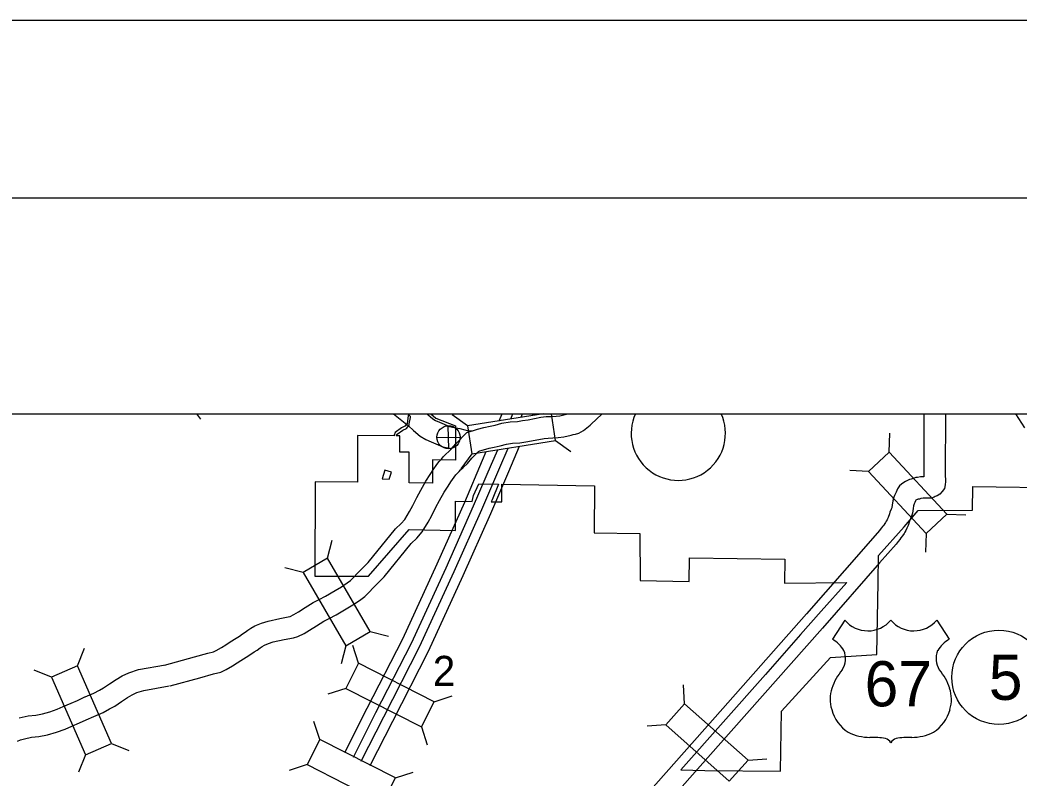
# Model space of a CAD drawing. Extents: x 1369979 to 1371646, y 379997 to 381064.
# Drawn here: x 1370321.9 to 1370431.4, y 380981.1 to 381064.1 of the extents above; entities that cross this region are included whole.
import ezdxf

# ---------------------------------------------------------------- set-up
doc = ezdxf.new("R2010")
doc.units = 0
for name, color, linetype in [('R_Border', 7, 'Continuous'), ('R_Border Notes', 7, 'Continuous'), ('R_No Plot', 7, 'Continuous')]:
    doc.layers.add(name, color=color, linetype=linetype)

msp = doc.modelspace()

# ---------------------------------------------------------------- linework, layer by layer
at = {"layer": 'R_Border'}
msp.add_line((1370040.95, 381044.6), (1371621.85, 381044.6), dxfattribs=at)
at = {"layer": 'R_Border Notes'}
for p, q in [((1370341.21, 381020.95), (1370341.66, 381020.34)), ((1370370.87, 381019.62), (1370369.2, 381020.83)), ((1370379.19, 381020.95), (1370370.87, 381019.62)), ((1370380.52, 381018.03), (1370380.06, 381020.95)), ((1370430.87, 381020.95), (1370431.83, 381019.4)), ((1370368.82, 381017.1), (1370368.77, 381019.64)), ((1370370.87, 381019.62), (1370371.36, 381016.57)), ((1370367.52, 381018.34), (1370370.07, 381018.4)), ((1370417.05, 381016.75), (1370417.12, 381018.81)), ((1370371.36, 381016.57), (1370380.52, 381018.03)), ((1370380.52, 381018.03), (1370382.19, 381016.82)), ((1370371.36, 381016.57), (1370370.15, 381014.9)), ((1370414.78, 381014.64), (1370412.72, 381014.72)), ((1370423.36, 381009.94), (1370425.42, 381009.86)), ((1370421.09, 381007.84), (1370421.01, 381005.78)), ((1370355.56, 381005.12), (1370356.08, 381007.11)), ((1370352.88, 381003.56), (1370350.89, 381004.08)), ((1370412.18, 380998.34), (1370410.83, 380996.25)), ((1370422.24, 380998.34), (1370423.59, 380996.25)), ((1370360.23, 380997.1), (1370362.23, 380996.58)), ((1370328.19, 380993.34), (1370328.94, 380995.26)), ((1370357.56, 380995.54), (1370357.04, 380993.55)), ((1370358.96, 380993.62), (1370358.32, 380995.58)), ((1370325.35, 380992.11), (1370323.43, 380992.86)), ((1370357.56, 380990.87), (1370355.6, 380990.23)), ((1370394.64, 380989.18), (1370394.51, 380991.24)), ((1370367.23, 380989.41), (1370369.19, 380990.05)), ((1370354.71, 380985.28), (1370354.07, 380987.24)), ((1370365.83, 380986.65), (1370366.47, 380984.69)), ((1370392.59, 380986.86), (1370390.53, 380986.74)), ((1370331.9, 380984.84), (1370333.82, 380984.08)), ((1370329.06, 380983.6), (1370328.31, 380981.68)), ((1370353.31, 380982.53), (1370351.34, 380981.89)), ((1370401.59, 380983.02), (1370403.64, 380983.15)), ((1370362.98, 380981.07), (1370364.94, 380981.7))]:
    msp.add_line(p, q, dxfattribs=at)
for points in [[(1370366.85, 381020.95), (1370367.42, 381020.45), (1370369.58, 381019.62), (1370369.58, 381018.43), (1370369.57, 381015.87), (1370367.04, 381015.91), (1370367.03, 381013.34), (1370364.49, 381013.38), (1370364.5, 381016.73), (1370363.47, 381016.74), (1370363.47, 381018.52), (1370363.08, 381018.52), (1370363.08, 381018.53), (1370363.09, 381018.58), (1370363.1, 381018.61), (1370363.11, 381018.64), (1370363.13, 381018.69), (1370363.19, 381018.73), (1370363.79, 381019.14), (1370364.19, 381019.35), (1370364.48, 381019.68), (1370364.5, 381019.83), (1370364.62, 381020.55), (1370364.63, 381020.65), (1370364.45, 381020.84), (1370364.4, 381020.74), (1370364.26, 381019.86), (1370364.25, 381019.85), (1370364.03, 381019.6), (1370364.02, 381019.59), (1370363.66, 381019.41), (1370362.95, 381018.88), (1370362.91, 381018.8), (1370362.88, 381018.7), (1370362.86, 381018.62), (1370362.85, 381018.53), (1370362.85, 381018.52), (1370358.83, 381018.55), (1370358.82, 381013.44), (1370354.19, 381013.49), (1370354.15, 381003.17), (1370360.04, 381003.15), (1370364.48, 381008.26), (1370369.55, 381008.17), (1370369.56, 381011.37), (1370371.37, 381011.35), (1370371.54, 381012.01), (1370372.1, 381013.26), (1370374.27, 381013.23), (1370373.59, 381011.52), (1370373.45, 381011.31), (1370374.62, 381011.29), (1370374.63, 381013.22), (1370384.77, 381013.06), (1370384.74, 381007.92), (1370389.75, 381007.85), (1370389.77, 381002.68), (1370395.14, 381002.58), (1370395.16, 381005.18), (1370405.6, 381005.01), (1370405.58, 381002.39), (1370412.38, 381002.46), (1370409.58, 380999.31), (1370407.34, 380996.77), (1370403.48, 380992.4), (1370394.24, 380981.94), (1370396.86, 380981.89), (1370405.12, 380981.81)], [(1370362.78, 381020.95), (1370364.43, 381019.61), (1370364.98, 381019.11), (1370365.7, 381018.49), (1370366.31, 381018.11), (1370366.9, 381017.86), (1370368.18, 381017.32), (1370368.71, 381017.2), (1370369.14, 381017.1)], [(1370366.44, 381020.95), (1370366.53, 381020.87), (1370367.09, 381020.38), (1370367.39, 381020.2), (1370367.81, 381020.02), (1370368.9, 381019.56), (1370369.23, 381019.49), (1370369.65, 381019.39), (1370370.04, 381019.33), (1370370.58, 381019.19), (1370370.83, 381019.13), (1370371.35, 381019.06)], [(1370370.81, 381018.9), (1370371.55, 381019.12), (1370371.97, 381019.25), (1370372.68, 381019.45), (1370373.35, 381019.6), (1370373.92, 381019.7), (1370374.64, 381019.91), (1370375.56, 381020.05), (1370376.35, 381020.1), (1370376.89, 381020.2), (1370377.5, 381020.28), (1370378.91, 381020.56), (1370379.5, 381020.63), (1370380.11, 381020.66), (1370380.6, 381020.68), (1370381, 381020.73), (1370381.71, 381020.89), (1370381.93, 381020.94), (1370381.96, 381020.95)], [(1370372.07, 381016.83), (1370372.24, 381016.88), (1370372.62, 381017), (1370373.25, 381017.18), (1370373.81, 381017.3), (1370374.45, 381017.42), (1370375.15, 381017.62), (1370375.81, 381017.72), (1370376.62, 381017.77), (1370377.26, 381017.88), (1370377.89, 381017.97), (1370379.26, 381018.25), (1370379.7, 381018.29), (1370380.21, 381018.32), (1370380.79, 381018.34), (1370381.41, 381018.42), (1370382.23, 381018.6), (1370382.46, 381018.66), (1370382.69, 381018.71), (1370383.05, 381018.81), (1370383.58, 381019.12), (1370384.31, 381019.69), (1370385.1, 381020.47), (1370385.48, 381020.81), (1370385.6, 381020.95)], [(1370374.36, 381020.18), (1370374.68, 381020.95)], [(1370375.62, 381020.4), (1370375.85, 381020.95)], [(1370376.76, 381020.58), (1370376.91, 381020.95)], [(1370378, 381020.77), (1370378.08, 381020.95)], [(1370420.83, 381020.95), (1370420.82, 381014.35), (1370420.83, 381014.05), (1370420.46, 381014.04), (1370420.15, 381013.98), (1370419.95, 381013.95), (1370419.77, 381013.89), (1370419.67, 381013.87), (1370419.44, 381013.8), (1370419.27, 381013.75), (1370419.03, 381013.64), (1370418.81, 381013.52), (1370418.62, 381013.41), (1370418.4, 381013.24), (1370418.18, 381013.04), (1370417.93, 381012.72), (1370417.79, 381012.37), (1370417.72, 381012.22), (1370417.62, 381011.99), (1370417.56, 381011.82), (1370417.42, 381011.41), (1370417.35, 381010.92), (1370417.32, 381010.67), (1370417.31, 381010.66), (1370417.25, 381010.51), (1370417.12, 381010.17), (1370417.07, 381009.97), (1370416.94, 381009.58), (1370416.86, 381009.43), (1370416.82, 381009.34), (1370416.72, 381009.19), (1370416.63, 381009.03), (1370416.56, 381008.91), (1370416.45, 381008.76), (1370416.34, 381008.62), (1370416.17, 381008.4), (1370415.99, 381008.17), (1370414.23, 381006.16), (1370407.98, 380999.02), (1370397.99, 380987.73), (1370389.22, 380977.83)], [(1370423.18, 381020.95), (1370423.17, 381014.36), (1370423.18, 381013.53), (1370423.15, 381013.16), (1370423.08, 381012.77), (1370422.84, 381012.42), (1370422.58, 381012.14), (1370422.3, 381011.97), (1370422.08, 381011.87), (1370421.96, 381011.83), (1370421.66, 381011.71), (1370421.02, 381011.72), (1370420.74, 381011.71), (1370420.54, 381011.66), (1370420.49, 381011.66), (1370420.37, 381011.61), (1370420.22, 381011.59), (1370420.14, 381011.56), (1370420.11, 381011.55), (1370420.08, 381011.54), (1370419.96, 381011.47), (1370419.95, 381011.47), (1370419.93, 381011.42), (1370419.85, 381011.24), (1370419.81, 381011.15), (1370419.78, 381011.08), (1370419.71, 381010.87), (1370419.67, 381010.58), (1370419.6, 381010.07), (1370419.5, 381009.83), (1370419.44, 381009.66), (1370419.35, 381009.43), (1370419.31, 381009.29), (1370419.12, 381008.7), (1370418.97, 381008.41), (1370418.86, 381008.16), (1370418.73, 381007.97), (1370418.66, 381007.84), (1370418.48, 381007.57), (1370418.32, 381007.36), (1370418.19, 381007.19), (1370418.02, 381006.97), (1370417.81, 381006.68), (1370415.99, 381004.61), (1370409.74, 380997.47), (1370399.74, 380986.17), (1370390.98, 380976.28)], [(1370337.71, 380993.42), (1370340.98, 380994.31), (1370342.46, 380994.71), (1370343.06, 380994.87), (1370343.38, 380995.02), (1370343.96, 380995.36), (1370344.42, 380995.64), (1370344.8, 380995.89), (1370345.38, 380996.26), (1370345.92, 380996.6), (1370346.23, 380996.83), (1370346.53, 380997.01), (1370346.82, 380997.23), (1370347.17, 380997.46), (1370347.61, 380997.71), (1370348.33, 380998.01), (1370349.04, 380998.22), (1370350.33, 380998.51), (1370351.26, 380998.69), (1370351.46, 380998.75), (1370351.88, 380998.95), (1370352.36, 380999.24), (1370353.1, 380999.71), (1370353.98, 381000.26), (1370354.64, 381000.61), (1370355.35, 381000.98), (1370356.39, 381001.59), (1370357.07, 381002), (1370357.72, 381002.42), (1370358.08, 381002.68), (1370358.42, 381003.04), (1370358.79, 381003.46), (1370360, 381004.67), (1370363, 381008.33), (1370363.62, 381008.92), (1370364.01, 381009.37), (1370364.54, 381010.26), (1370364.9, 381010.91), (1370365.33, 381011.79), (1370365.77, 381012.59), (1370366.32, 381013.55), (1370366.78, 381014.29), (1370367.12, 381014.82), (1370367.53, 381015.38), (1370367.78, 381015.73), (1370368.02, 381015.99), (1370368.23, 381016.24), (1370368.51, 381016.52), (1370368.83, 381016.8), (1370369.14, 381017.09), (1370369.59, 381017.64), (1370370.81, 381018.9)], [(1370359.25, 380982.88), (1370361.73, 380987.76), (1370365.63, 380995.41), (1370369.42, 381003.67), (1370372.44, 381010.46), (1370374.42, 381015.06), (1370375.32, 381017.18)], [(1370360.22, 380982.43), (1370362.69, 380987.27), (1370366.59, 380994.94), (1370370.39, 381003.22), (1370373.43, 381010.03), (1370375.41, 381014.64), (1370376.57, 381017.39)], [(1370338.33, 380991.16), (1370341.59, 380992.04), (1370343.08, 380992.45), (1370343.87, 380992.66), (1370344.47, 380992.94), (1370345.16, 380993.35), (1370345.66, 380993.65), (1370346.07, 380993.92), (1370346.64, 380994.28), (1370347.26, 380994.68), (1370347.52, 380994.87), (1370347.84, 380995.05), (1370348.17, 380995.31), (1370348.4, 380995.46), (1370348.66, 380995.61), (1370349.11, 380995.8), (1370349.62, 380995.95), (1370350.81, 380996.21), (1370351.82, 380996.41), (1370352.31, 380996.56), (1370353, 380996.89), (1370353.59, 380997.25), (1370354.35, 380997.73), (1370355.14, 380998.23), (1370355.73, 380998.53), (1370356.49, 380998.93), (1370357.59, 380999.57), (1370358.31, 381000.01), (1370359.05, 381000.48), (1370359.64, 381000.92), (1370360.16, 381001.46), (1370360.5, 381001.86), (1370361.74, 381003.09), (1370364.72, 381006.73), (1370365.33, 381007.31), (1370365.92, 381008), (1370366.57, 381009.09), (1370366.98, 381009.82), (1370367.41, 381010.7), (1370367.82, 381011.45), (1370368.33, 381012.35), (1370368.76, 381013.03), (1370369.06, 381013.5), (1370369.41, 381013.99), (1370369.61, 381014.25), (1370369.77, 381014.44), (1370369.95, 381014.63), (1370370.12, 381014.82), (1370370.41, 381015.07), (1370370.86, 381015.49), (1370371.34, 381016.08), (1370372.07, 381016.83)], [(1370357.44, 380983.86), (1370359.91, 380988.69), (1370363.78, 380996.3), (1370367.55, 381004.51), (1370370.57, 381011.28), (1370372.53, 381015.86), (1370372.93, 381016.8)], [(1370358.38, 380983.34), (1370360.86, 380988.21), (1370364.75, 380995.83), (1370368.53, 381004.07), (1370371.55, 381010.85), (1370373.52, 381015.44), (1370374.18, 381016.99)], [(1370405.12, 380981.81), (1370405.26, 380988.37), (1370410.6, 380994.26), (1370415.68, 380994.58), (1370415.83, 381002.5), (1370415.86, 381005.43), (1370418.66, 381008.57), (1370420.19, 381010.36), (1370426.16, 381010.4), (1370426.18, 381012.99), (1370436.43, 381012.82)], [(1370329.02, 380989.94), (1370329.96, 380990.35), (1370330.59, 380990.68), (1370331.04, 380990.93), (1370331.7, 380991.37), (1370332.43, 380991.86), (1370333.07, 380992.23), (1370333.81, 380992.59), (1370334.88, 380992.92), (1370337.81, 380993.44)], [(1370329.96, 380987.79), (1370330.98, 380988.24), (1370331.7, 380988.62), (1370332.26, 380988.93), (1370333, 380989.42), (1370333.67, 380989.87), (1370334.17, 380990.16), (1370334.67, 380990.4), (1370335.43, 380990.64), (1370338.23, 380991.14)], [(1370321.8, 380987.64), (1370322.8, 380987.85), (1370323.62, 380987.93), (1370324.36, 380988.07), (1370325.16, 380988.3), (1370325.96, 380988.59), (1370326.62, 380988.89), (1370327.49, 380989.25), (1370328.19, 380989.56), (1370329, 380989.93)], [(1370321.62, 380985.07), (1370321.96, 380985.24), (1370322.37, 380985.36), (1370323.17, 380985.53), (1370323.97, 380985.61), (1370324.9, 380985.79), (1370325.88, 380986.07), (1370326.84, 380986.42), (1370327.56, 380986.74), (1370328.41, 380987.1), (1370329.14, 380987.42), (1370329.97, 380987.8)]]:
    msp.add_lwpolyline(points, dxfattribs=at)
for points in [[(1370414.78, 381014.64), (1370421.09, 381007.84), (1370423.36, 381009.94), (1370417.05, 381016.75)], [(1370362.29, 381013.77), (1370362.54, 381014.54), (1370361.83, 381014.76), (1370361.52, 381013.82)], [(1370352.88, 381003.56), (1370357.56, 380995.54), (1370360.23, 380997.1), (1370355.56, 381005.12)], [(1370325.35, 380992.11), (1370329.06, 380983.6), (1370331.9, 380984.84), (1370328.19, 380993.34)], [(1370367.23, 380989.41), (1370358.96, 380993.62), (1370357.56, 380990.87), (1370365.83, 380986.65)], [(1370392.59, 380986.86), (1370399.53, 380980.71), (1370401.59, 380983.02), (1370394.64, 380989.18)], [(1370362.98, 380981.07), (1370354.71, 380985.28), (1370353.31, 380982.53), (1370361.57, 380978.31)]]:
    msp.add_lwpolyline(points, close=True, dxfattribs=at)
for centre, radius in [((1370368.8, 381018.37), 1.27), ((1370429.05, 380992.08), 5.16)]:
    msp.add_circle(centre, radius, dxfattribs=at)
for centre, radius, start, end in [((1370393.95, 381018.81), 5.16, 155.4795, 24.5205), ((1370414.7, 381000.46), 3.29, 220.075, 319.6701), ((1370419.72, 381000.46), 3.29, 220.3299, 319.925), ((1370409.07, 380993.21), 3.51, 30.7809, 59.9883), ((1370425.36, 380993.21), 3.51, 120.0117, 149.2191), ((1370409.84, 380994.14), 2.41, 328.8105, 21.2108), ((1370424.58, 380994.14), 2.41, 158.7892, 211.1895), ((1370416.14, 380989.2), 5.62, 138.9565, 162.6913), ((1370418.29, 380989.2), 5.62, 17.3087, 41.0435), ((1370414.28, 380989.66), 3.71, 160.9576, 197.3819), ((1370420.14, 380989.66), 3.71, 342.6181, 19.0424), ((1370414.89, 380989.67), 4.3, 195.1074, 237.1312), ((1370419.54, 380989.67), 4.3, 302.8688, 344.8926), ((1370414.97, 380991.02), 5.52, 244.0771, 269.5779), ((1370415.09, 380975.4), 10.1, 81.1942, 90.9539), ((1370416.36, 380984.46), 0.968, 28.0342, 72.9864), ((1370418.07, 380984.46), 0.968, 107.0136, 151.9658), ((1370419.33, 380975.4), 10.1, 89.0461, 98.8058), ((1370419.46, 380991.02), 5.52, 270.4221, 295.9229)]:
    msp.add_arc(centre, radius, start, end, dxfattribs=at)
at = {"layer": 'R_No Plot'}
msp.add_line((1369978.95, 381064.07), (1371645.61, 381064.07), dxfattribs=at)
for points in [[(1369978.91, 381064.07), (1371645.61, 381064.07), (1371645.61, 379997.39), (1369978.91, 379997.39)], [(1370052.8, 381020.95), (1370474.58, 381020.95), (1370474.58, 380650.53), (1370052.8, 380650.53)]]:
    msp.add_lwpolyline(points, close=True, dxfattribs=at)

# ---------------------------------------------------------------- texts
at = {"layer": 'R_Border Notes'}
for s, height, p in [('2', 3.3, (1370367.08, 380991.13)), ('5', 4.95, (1370427.94, 380989.61)), ('67', 4.95, (1370414.35, 380988.9))]:
    msp.add_text(s, height=height, dxfattribs=at).set_placement(p)

doc.saveas('drawing.dxf')
